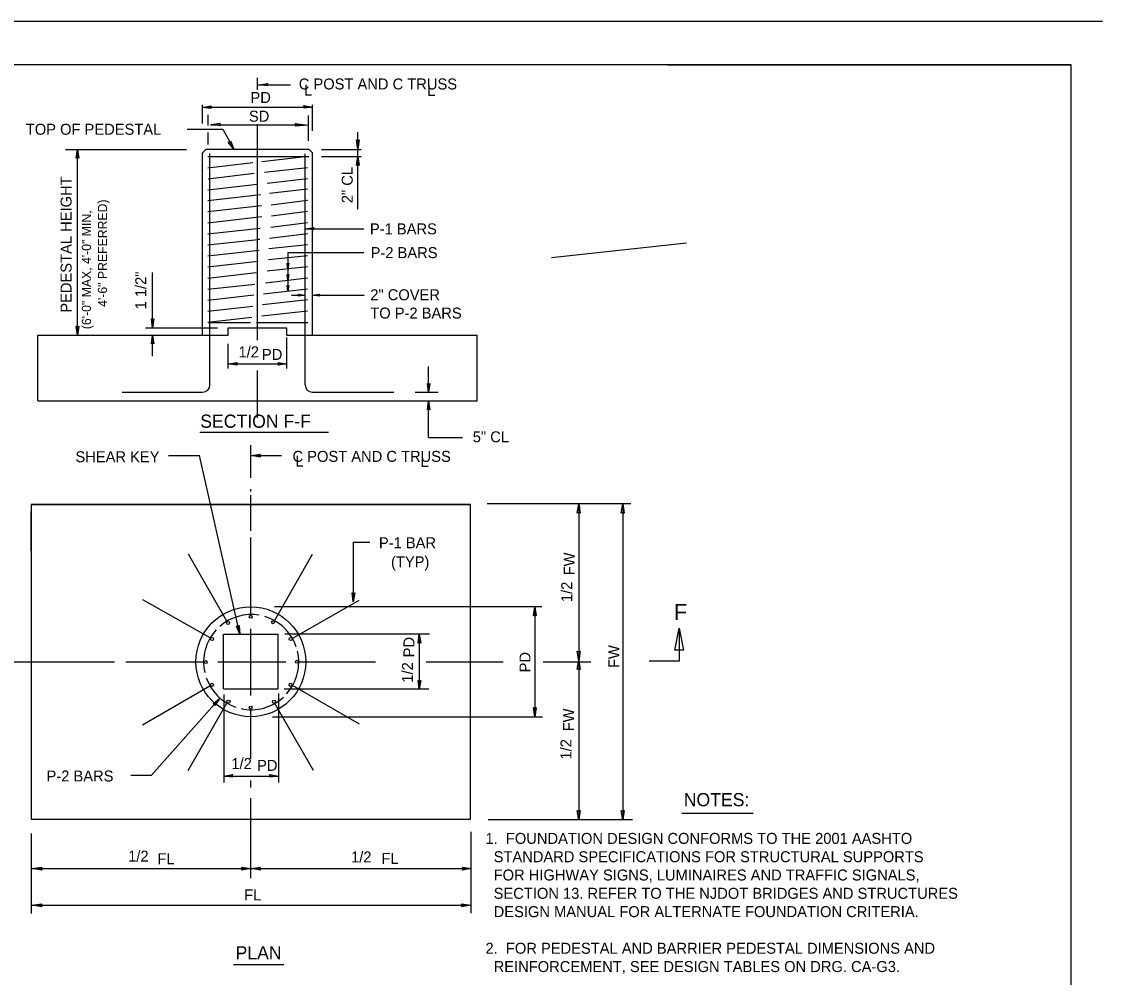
# Model space of a CAD drawing. Extents: x -3 to 26050223, y 0 to 12035012.
# Drawn here: x 44.29 to 68.89, y 21.57 to 43.33 of the extents above; entities that cross this region are included whole.
import ezdxf

# ---------------------------------------------------------------- set-up
doc = ezdxf.new("R2010")
doc.units = 0
for name, color, linetype in [('1', 7, 'Continuous'), ('2', 7, 'Continuous'), ('39', 7, 'Continuous')]:
    doc.layers.add(name, color=color, linetype=linetype)

msp = doc.modelspace()

# ---------------------------------------------------------------- linework, layer by layer
at = {"layer": '1'}
for p, q in [((68.892, 43.325), (0, 43.325)), ((68.183, 42.342), (3.6, 42.342)), ((68.183, 1.017), (68.183, 42.342)), ((48.341, 33.978), (51.275, 33.978)), ((49.108, 21.865), (50.258, 21.865))]:
    msp.add_line(p, q, dxfattribs=at)
at = {"layer": '39'}
for p, q in [((58.992, 42.342), (68.183, 42.342)), ((49.658, 41.773), (49.658, 42.042)), ((49.66, 41.887), (50.41, 41.887)), ((48.408, 41.008), (48.408, 41.433)), ((48.418, 41.376), (50.901, 41.376)), ((50.908, 40.842), (50.908, 41.433)), ((48.537, 40.963), (48.537, 41.201)), ((50.815, 40.615), (50.815, 41.191)), ((48.058, 40.875), (48.867, 40.875)), ((48.588, 40.974), (50.759, 40.974)), ((48.867, 40.875), (49.117, 40.425)), ((49.658, 36.075), (49.658, 40.992)), ((48.531, 40.525), (48.531, 40.801)), ((51.942, 40.267), (51.942, 40.808)), ((45.283, 40.417), (48.042, 40.417)), ((45.558, 36.192), (45.558, 40.417)), ((48.408, 40.342), (48.492, 40.425)), ((48.492, 40.425), (50.825, 40.425)), ((48.492, 40.425), (50.825, 40.425)), ((50.908, 40.342), (50.825, 40.425)), ((51.117, 40.417), (52.017, 40.417)), ((48.408, 36.192), (48.408, 40.342)), ((48.525, 40.258), (50.825, 40.258)), ((48.525, 40), (49.55, 40.117)), ((48.575, 35.808), (48.575, 40.325)), ((49.758, 40.142), (50.742, 40.258)), ((50.742, 35.767), (50.742, 40.317)), ((50.908, 36.192), (50.908, 40.342)), ((51.117, 40.258), (52.017, 40.258)), ((51.942, 39.058), (51.942, 40.258)), ((48.533, 39.75), (49.583, 39.875)), ((49.817, 39.9), (50.792, 40.008)), ((48.525, 39.5), (49.65, 39.625)), ((49.875, 39.65), (50.792, 39.758)), ((48.525, 39.25), (49.725, 39.392)), ((49.933, 39.417), (50.792, 39.517)), ((48.525, 39), (49.75, 39.142)), ((49.967, 39.158), (50.792, 39.258)), ((50.783, 39.258), (50.792, 39.258)), ((48.525, 38.742), (49.758, 38.892)), ((49.975, 38.908), (50.792, 39.008)), ((49.958, 38.65), (50.792, 38.75)), ((48.525, 38.492), (49.717, 38.625)), ((49.933, 38.4), (50.792, 38.5)), ((50.742, 38.608), (52.075, 38.608)), ((48.525, 38.242), (49.667, 38.367)), ((49.675, 38.375), (49.708, 38.375)), ((49.917, 38.158), (50.792, 38.25)), ((56.35, 37.958), (59.425, 38.292)), ((48.525, 37.992), (49.692, 38.125)), ((49.908, 37.908), (50.792, 38)), ((50.35, 38.067), (50.35, 37.192)), ((50.35, 38.067), (52.075, 38.067)), ((48.525, 37.742), (49.675, 37.875)), ((49.875, 37.65), (50.792, 37.75)), ((47.267, 36.358), (47.267, 37.617)), ((48.525, 37.483), (49.625, 37.617)), ((49.842, 37.383), (50.792, 37.492)), ((48.525, 37.233), (49.6, 37.35)), ((49.792, 37.133), (50.792, 37.242)), ((48.525, 36.983), (49.575, 37.108)), ((49.775, 36.883), (50.792, 37)), ((50.433, 37.1), (50.742, 37.1)), ((50.908, 37.1), (52.083, 37.1)), ((48.525, 36.733), (49.55, 36.85)), ((49.758, 36.625), (50.792, 36.742)), ((48.525, 36.483), (49.525, 36.6)), ((48.542, 36.475), (49.5, 36.475)), ((49.633, 36.475), (50.8, 36.475)), ((44.658, 34.692), (44.658, 36.192)), ((44.658, 36.192), (48.992, 36.192)), ((47.108, 36.358), (48.75, 36.358)), ((47.267, 35.708), (47.267, 36.192)), ((48.992, 36.192), (48.992, 36.358)), ((48.992, 36.358), (50.325, 36.358)), ((50.325, 36.192), (50.325, 36.358)), ((50.325, 36.192), (54.658, 36.192)), ((54.658, 34.692), (54.658, 36.192)), ((48.992, 35.433), (48.992, 35.992)), ((50.325, 35.433), (50.325, 36.133)), ((48.575, 35.058), (48.575, 35.817)), ((50.742, 35.058), (50.742, 35.767)), ((48.992, 35.533), (50.325, 35.533)), ((53.55, 34.892), (53.55, 35.475)), ((49.658, 34.308), (49.658, 35.383)), ((46.575, 34.892), (48.408, 34.892)), ((50.908, 34.892), (52.758, 34.892)), ((53.25, 34.892), (53.767, 34.892)), ((44.658, 34.692), (54.658, 34.692)), ((53.55, 33.858), (53.55, 34.692)), ((53.55, 33.858), (54.325, 33.858)), ((49.505, 32.938), (49.505, 33.688)), ((47.63, 33.447), (48.338, 33.447)), ((49.255, 29.38), (48.338, 33.447)), ((49.505, 33.447), (50.205, 33.447)), ((49.505, 32.63), (49.505, 32.68)), ((49.505, 31.738), (49.505, 32.547)), ((44.505, 32.338), (54.505, 32.338)), ((54.505, 32.338), (44.505, 32.338)), ((44.505, 32.338), (44.505, 25.172)), ((54.505, 25.172), (54.505, 32.338)), ((58.155, 32.347), (54.888, 32.347)), ((56.972, 32.347), (56.972, 28.78)), ((57.972, 32.347), (57.972, 25.155)), ((44.505, 31.272), (44.505, 32.172)), ((54.505, 31.805), (54.505, 32.122)), ((49.505, 29.83), (49.505, 31.58)), ((51.838, 31.48), (51.838, 30.122)), ((51.838, 31.48), (52.213, 31.48)), ((48.963, 29.68), (48.088, 31.205)), ((50.047, 29.688), (50.913, 31.205)), ((48.58, 29.297), (47.047, 30.163)), ((50.447, 29.288), (51.972, 30.155)), ((56.13, 30.005), (50.047, 30.005)), ((55.972, 30.005), (55.972, 27.497)), ((56.972, 30.005), (56.972, 27.497)), ((57.972, 30.005), (57.972, 27.497)), ((48.88, 29.38), (50.13, 29.38)), ((48.88, 28.138), (48.88, 29.38)), ((49.505, 27.988), (49.505, 29.505)), ((50.13, 28.138), (50.13, 29.38)), ((53.572, 29.38), (50.28, 29.38)), ((53.338, 29.38), (53.338, 28.13)), ((59.155, 29.022), (59.255, 29.522)), ((59.155, 29.022), (59.255, 29.522)), ((59.255, 29.522), (59.355, 29.022)), ((59.255, 29.522), (59.355, 29.022)), ((59.255, 29.497), (59.255, 28.772)), ((56.972, 28.788), (56.972, 25.155)), ((59.355, 29.022), (59.155, 29.022)), ((59.355, 29.022), (59.155, 29.022)), ((43.08, 28.755), (46.405, 28.755)), ((46.663, 28.755), (48.43, 28.755)), ((48.755, 28.755), (50.305, 28.755)), ((50.597, 28.755), (52.347, 28.755)), ((53.497, 28.755), (55.247, 28.755)), ((56.163, 28.755), (57.247, 28.755)), ((59.255, 28.772), (58.572, 28.772)), ((47.038, 27.322), (48.572, 28.205)), ((48.88, 28.138), (50.13, 28.138)), ((53.555, 28.13), (50.263, 28.13)), ((51.98, 27.338), (50.455, 28.213)), ((47.247, 26.172), (48.797, 27.93)), ((48.08, 26.28), (48.963, 27.813)), ((48.888, 28.013), (48.888, 26.005)), ((50.93, 26.28), (50.055, 27.805)), ((50.138, 28.03), (50.138, 26.005)), ((47.863, 27.797), (47.872, 27.797)), ((49.505, 26.547), (49.505, 27.663)), ((56.147, 27.497), (49.997, 27.497)), ((46.772, 26.172), (47.247, 26.172)), ((48.888, 26.155), (50.138, 26.155)), ((49.505, 25.897), (49.505, 26.055)), ((49.505, 23.83), (49.505, 25.647)), ((44.505, 25.172), (54.505, 25.172)), ((58.197, 25.155), (54.905, 25.155)), ((59.319, 25.309), (60.944, 25.309)), ((54.513, 24.888), (54.513, 23.03)), ((44.505, 24.847), (44.505, 23.022)), ((44.53, 24.047), (49.505, 24.047)), ((49.505, 24.047), (54.53, 24.047)), ((44.53, 23.213), (54.513, 23.213))]:
    msp.add_line(p, q, dxfattribs=at)
for points in [[(49.878, 41.885), (49.895, 41.86), (49.695, 41.885), (49.895, 41.918)], [(48.582, 41.372), (48.599, 41.347), (48.399, 41.372), (48.599, 41.405)], [(50.727, 41.381), (50.711, 41.414), (50.911, 41.381), (50.711, 41.356)], [(48.789, 40.98), (48.806, 40.955), (48.606, 40.98), (48.806, 41.013)], [(50.54, 40.972), (50.515, 41.005), (50.815, 40.972), (50.515, 40.947)], [(49.025, 40.583), (49.042, 40.608), (49.117, 40.425), (48.992, 40.583)], [(49.025, 40.583), (49.042, 40.608), (49.117, 40.425), (48.992, 40.583)], [(51.942, 40.608), (51.975, 40.633), (51.942, 40.417), (51.908, 40.633)], [(45.558, 40.233), (45.533, 40.217), (45.558, 40.417), (45.592, 40.217)], [(45.558, 40.233), (45.533, 40.217), (45.558, 40.417), (45.592, 40.217)], [(45.558, 40.233), (45.533, 40.217), (45.558, 40.417), (45.592, 40.217)], [(51.942, 40.067), (51.908, 40.05), (51.942, 40.258), (51.975, 40.05)], [(50.925, 38.608), (50.942, 38.583), (50.742, 38.608), (50.942, 38.642)], [(50.35, 37.95), (50.35, 37.95), (50.35, 37.95), (50.35, 37.95)], [(50.35, 37.817), (50.367, 37.825), (50.35, 37.7), (50.333, 37.825)], [(50.35, 37.558), (50.367, 37.567), (50.35, 37.442), (50.333, 37.567)], [(50.35, 37.308), (50.367, 37.317), (50.35, 37.192), (50.333, 37.317)], [(50.6, 37.1), (50.583, 37.125), (50.742, 37.1), (50.583, 37.075)], [(51.05, 37.1), (51.067, 37.075), (50.908, 37.1), (51.067, 37.125)], [(47.267, 36.542), (47.3, 36.558), (47.267, 36.358), (47.242, 36.558)], [(47.267, 36.542), (47.3, 36.558), (47.267, 36.358), (47.242, 36.558)], [(45.558, 36.375), (45.592, 36.392), (45.558, 36.192), (45.533, 36.392)], [(47.267, 36.008), (47.242, 35.992), (47.267, 36.192), (47.3, 35.992)], [(49.175, 35.533), (49.192, 35.508), (48.992, 35.533), (49.192, 35.567)], [(50.142, 35.533), (50.125, 35.567), (50.325, 35.533), (50.125, 35.508)], [(53.55, 35.075), (53.583, 35.092), (53.55, 34.892), (53.525, 35.092)], [(53.55, 34.508), (53.525, 34.492), (53.55, 34.692), (53.583, 34.492)], [(49.697, 33.447), (49.722, 33.413), (49.505, 33.447), (49.722, 33.48)], [(49.697, 33.447), (49.722, 33.413), (49.505, 33.447), (49.722, 33.48)], [(56.972, 32.155), (56.938, 32.138), (56.972, 32.347), (57.005, 32.138)], [(57.972, 32.155), (57.938, 32.138), (57.972, 32.347), (58.005, 32.138)], [(51.838, 30.305), (51.872, 30.322), (51.838, 30.122), (51.813, 30.322)], [(55.972, 29.813), (55.938, 29.797), (55.972, 30.005), (56.005, 29.797)], [(49.213, 29.555), (49.238, 29.58), (49.255, 29.38), (49.18, 29.563)], [(53.338, 29.197), (53.313, 29.18), (53.338, 29.38), (53.372, 29.18)], [(53.338, 29.197), (53.313, 29.18), (53.338, 29.38), (53.372, 29.18)], [(56.972, 28.972), (57.005, 28.997), (56.972, 28.78), (56.938, 28.997)], [(56.972, 28.597), (56.938, 28.58), (56.972, 28.788), (57.005, 28.58)], [(53.338, 28.313), (53.372, 28.33), (53.338, 28.13), (53.313, 28.33)], [(53.338, 28.313), (53.372, 28.33), (53.338, 28.13), (53.313, 28.33)], [(48.68, 27.797), (48.647, 27.797), (48.797, 27.93), (48.688, 27.763)], [(55.972, 27.688), (56.005, 27.713), (55.972, 27.497), (55.938, 27.713)], [(49.072, 26.155), (49.088, 26.13), (48.888, 26.155), (49.088, 26.188)], [(49.072, 26.155), (49.088, 26.13), (48.888, 26.155), (49.088, 26.188)], [(49.955, 26.155), (49.938, 26.188), (50.138, 26.155), (49.938, 26.13)], [(56.972, 25.347), (57.005, 25.372), (56.972, 25.155), (56.938, 25.372)], [(57.972, 25.347), (58.005, 25.372), (57.972, 25.155), (57.938, 25.372)], [(44.722, 24.047), (44.747, 24.013), (44.53, 24.047), (44.747, 24.08)], [(49.313, 24.047), (49.297, 24.08), (49.505, 24.047), (49.297, 24.013)], [(49.697, 24.047), (49.722, 24.013), (49.505, 24.047), (49.722, 24.08)], [(54.338, 24.047), (54.322, 24.08), (54.53, 24.047), (54.322, 24.013)], [(44.722, 23.213), (44.747, 23.18), (44.53, 23.213), (44.747, 23.247)], [(54.322, 23.213), (54.305, 23.247), (54.513, 23.213), (54.305, 23.18)]]:
    msp.add_lwpolyline(points, close=True, dxfattribs=at)
for centre, radius in [((49.505, 28.755), 1.25), ((49.505, 29.78), 0.0344), ((48.988, 29.638), 0.0344), ((50.013, 29.655), 0.0344), ((48.622, 29.272), 0.0344), ((50.413, 29.272), 0.0344), ((50.555, 28.755), 0.0344), ((48.48, 28.747), 0.0344), ((48.622, 28.23), 0.0344), ((50.413, 28.23), 0.0344), ((48.997, 27.847), 0.0344), ((50.03, 27.847), 0.0344), ((49.505, 27.713), 0.0344)]:
    msp.add_circle(centre, radius, dxfattribs=at)
for centre, radius, start, end in [((48.408, 35.058), 0.167, 270, 0), ((50.908, 35.058), 0.167, 180, 270), ((49.513, 28.747), 1.083, 80.2569, 131.4173), ((49.513, 28.747), 1.083, 18.8491, 73.3856), ((49.513, 28.747), 1.083, 137.5169, 192.4381), ((49.513, 28.747), 1.083, 318.2583, 13.3424), ((49.513, 28.747), 1.083, 199.2693, 251.1509), ((49.513, 28.747), 1.083, 257.7537, 312.6037)]:
    msp.add_arc(centre, radius, start, end, dxfattribs=at)

# ---------------------------------------------------------------- texts
at = {"layer": '1'}
msp.add_text('F', height=0.367, dxfattribs=at).set_placement((59.138, 29.705))
at = {"layer": '2'}
for s, p in [('C POST AND C TRUSS', (50.597, 41.781)), ('L', (50.719, 41.642)), ('L', (53.522, 41.632)), ('PD', (49.498, 41.473)), ('SD', (49.462, 41.047)), ('TOP OF PEDESTAL', (44.383, 40.75)), ('P-1 BARS', (52.217, 38.483)), ('P-2 BARS', (52.233, 37.942)), ('2" COVER', (52.225, 36.983)), ('TO P-2 BARS', (52.225, 36.567)), ('1/2', (49.225, 35.683)), ('PD', (49.758, 35.625)), ('5" CL', (54.558, 33.75)), ('SHEAR KEY', (45.513, 33.297)), ('C POST AND C TRUSS', (50.455, 33.305)), ('L', (50.522, 33.197)), ('L', (53.37, 33.187)), ('P-1 BAR', (52.422, 31.338)), ('(TYP)', (52.697, 30.905)), ('1/2', (49.063, 26.313)), ('PD', (49.647, 26.272)), ('P-2 BARS', (44.855, 26.03)), ('1/2', (46.713, 24.205)), ('FL', (47.38, 24.147)), ('1/2', (51.788, 24.188)), ('FL', (52.48, 24.155)), ('FL', (49.355, 23.322))]:
    msp.add_text(s, height=0.25, dxfattribs=at).set_placement(p)
for s, height, p in [('2" CL', 0.25, (51.825, 39.192)), ('PEDESTAL HEIGHT', 0.25, (45.425, 36.7)), ('4\'-6" PREFERRED)', 0.20835, (46.233, 36.833)), ('(6\'-0" MAX, 4\'-0" MIN,', 0.20835, (45.867, 36.325)), ('1 1/2"', 0.25, (47.125, 36.775)), ('FW', 0.25, (56.88, 30.722)), ('1/2', 0.25, (56.822, 30.113)), ('PD', 0.25, (53.23, 28.855)), ('FW', 0.25, (57.897, 28.613)), ('PD', 0.25, (55.872, 28.513)), ('1/2', 0.25, (53.197, 28.28)), ('FW', 0.25, (56.863, 27.172)), ('1/2', 0.25, (56.805, 26.53))]:
    msp.add_text(s, height=height, rotation=90, dxfattribs=at).set_placement(p)
at = {"layer": '39'}
for s, height, p in [('SECTION F-F', 0.3, (48.354, 34.081)), ('NOTES:', 0.3, (59.361, 25.467)), ('1.  FOUNDATION DESIGN CONFORMS TO THE 2001 AASHTO', 0.25, (54.848, 24.61)), ('  STANDARD SPECIFICATIONS FOR STRUCTURAL SUPPORTS ', 0.25, (54.848, 24.193)), ('  FOR HIGHWAY SIGNS, LUMINAIRES AND TRAFFIC SIGNALS, ', 0.25, (54.848, 23.777)), ('  SECTION 13. REFER TO THE NJDOT BRIDGES AND STRUCTURES', 0.25, (54.848, 23.36)), ('  DESIGN MANUAL FOR ALTERNATE FOUNDATION CRITERIA.', 0.25, (54.848, 22.943)), ('PLAN', 0.3, (49.158, 21.982)), ('2.  FOR PEDESTAL AND BARRIER PEDESTAL DIMENSIONS AND', 0.25, (54.848, 22.11)), ('  REINFORCEMENT, SEE DESIGN TABLES ON DRG. CA-G3.', 0.25, (54.848, 21.693))]:
    msp.add_text(s, height=height, dxfattribs=at).set_placement(p)

doc.saveas('drawing.dxf')
